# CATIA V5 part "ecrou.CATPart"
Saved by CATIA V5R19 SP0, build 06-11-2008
Part number: Part4.1
Bounding box of the stored display mesh (mm): x -5 to 5, y -29.998 to 29.998, z -26.158 to 26.158
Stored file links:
  F:\20\ecrou.CATPart
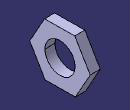
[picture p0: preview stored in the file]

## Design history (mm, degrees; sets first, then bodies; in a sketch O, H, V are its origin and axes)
Body1 (main body)
  Sketch1 on yz-plane, origin (0, 0, 0), H (0, 1, 0), V (0, 0, 1)
    point P1 (29.9979, 0.3591)
    point P2 (14.6879, 26.1585)
    point P3 (-15.3099, 25.7994)
    point P4 (-29.9979, -0.3591)
    point P5 (-14.6879, -26.1585)
    point P6 (15.3099, -25.7994)
    point P7 (22.3429, 13.2588)
    line L1 (29.9979, 0.3591) -> (14.6879, 26.1585)
    line L2 (14.6879, 26.1585) -> (-15.3099, 25.7994)
    line L3 (-15.3099, 25.7994) -> (-29.9979, -0.3591)
    line L4 (-29.9979, -0.3591) -> (-14.6879, -26.1585)
    line L5 (-14.6879, -26.1585) -> (15.3099, -25.7994)
    line L6 (15.3099, -25.7994) -> (29.9979, 0.3591)
    construction line L7 (0, 0) -> (22.3429, 13.2588)
    construction circle A1 centre (0, 0) radius 30
    construction arc A2 centre (-14.6879, -26.1585) radius 30 from (-29.9979, -0.3591) to (15.3099, -25.7994) cw
    construction arc A3 centre (14.6879, 26.1585) radius 30 from (-15.3099, 25.7994) to (29.9979, 0.3591) ccw
    circle A4 centre (0, 0) radius 15
    radius A4 = 15
    distance P3 P6 = 60
    coincidence: A1 P1, A1 P2, A1 P3, A1 P4, A1 P5, A1 P6, A2 O, A3 O
    midpoint: P7 L1
    parallelism: L1 L4
  Pad1: profile Sketch1, direction (1, 0, 0), length 5, mirrored extent
  Point1: type Center, Curve edge [face of Pad1 from Sketch1.A4 | start face of Pad1]
  Line1: type Normal, RefSkin start face of Pad1, Start 0, End 20, RefPoint Point1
